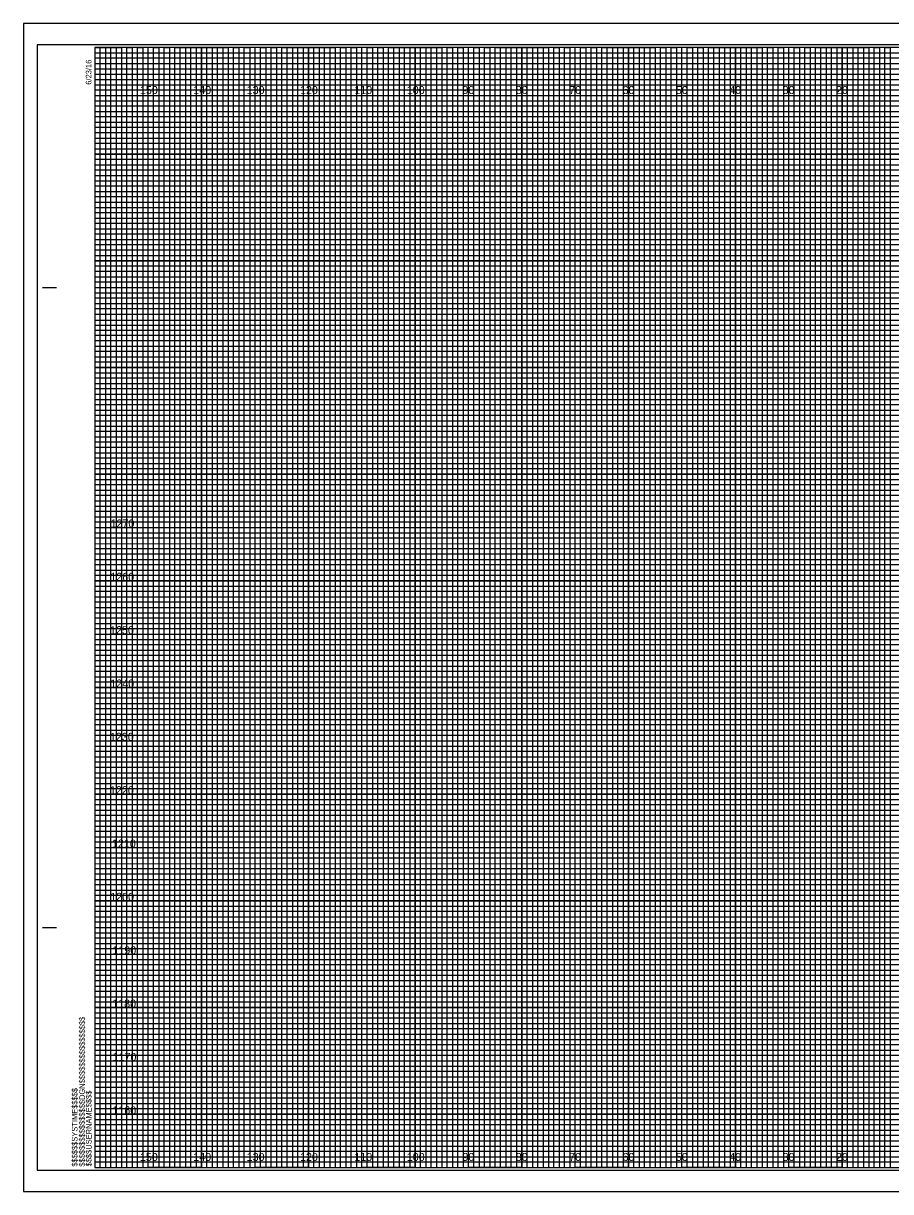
# Model space of a CAD drawing. Extents: x -13 to 323, y 215 to 434.
# Drawn here: x -13.4 to 149.1, y 215.5 to 434.5 of the extents above; entities that cross this region are included whole.
import ezdxf

# ---------------------------------------------------------------- set-up
doc = ezdxf.new("R2010")
doc.units = 0
for name, color, linetype in [('Exist Cross Section Cell', 7, 'Continuous'), ('Exist XS Center Line Elevation Label', 7, 'Continuous'), ('Exist XS Ground Line', 7, 'Continuous'), ('Prop XS Finish Grade', 7, 'Continuous'), ('Prop XS Finish Grade Earthwork', 7, 'Continuous'), ('Prop XS Finish Grade Pavement', 7, 'Continuous'), ('Prop XS Side Slope Text', 7, 'Continuous'), ('Prop XS Subgrade Earthwork', 7, 'Continuous'), ('Prop XSC Text', 7, 'Continuous'), ('Scratch_Level_5', 7, 'Continuous'), ('Typical Curb CELL', 7, 'Continuous')]:
    doc.layers.add(name, color=color, linetype=linetype)

msp = doc.modelspace()

# ---------------------------------------------------------------- linework, layer by layer
at = {"layer": 'Exist Cross Section Cell'}
for points in [[(0, 430), (5, 430), (5, 220), (15, 220), (15, 430), (25, 430), (25, 220), (35, 220), (35, 430), (45, 430), (45, 220), (55, 220), (55, 430), (65, 430), (65, 220), (75, 220), (75, 430), (85, 430), (85, 220), (95, 220), (95, 430), (105, 430), (105, 220), (115, 220), (115, 430), (125, 430), (125, 220), (135, 220), (135, 430), (145, 430), (145, 220), (155, 220)], [(0, 425), (275, 425)], [(0, 405), (320, 405), (320, 415), (0, 415)], [(0, 385), (320, 385), (320, 395), (0, 395)], [(0, 365), (320, 365), (320, 375), (0, 375)], [(0, 345), (320, 345), (320, 355), (0, 355)], [(0, 325), (320, 325), (320, 335), (0, 335)], [(0, 305), (320, 305), (320, 315), (0, 315)], [(0, 285), (320, 285), (320, 295), (0, 295)], [(0, 265), (320, 265), (320, 275), (0, 275)], [(0, 245), (320, 245), (320, 255), (0, 255)], [(0, 225), (320, 225), (320, 235), (0, 235)]]:
    msp.add_lwpolyline(points, dxfattribs=at)
at = {"layer": 'Exist XS Center Line Elevation Label'}
for p, q in [((10, 430), (0, 430)), ((10, 220), (10, 430)), ((30, 430), (20, 430)), ((20, 430), (20, 220)), ((30, 220), (30, 430)), ((50, 430), (40, 430)), ((40, 430), (40, 220)), ((50, 220), (50, 430)), ((70, 430), (60, 430)), ((60, 430), (60, 220)), ((70, 220), (70, 430)), ((90, 430), (80, 430)), ((80, 430), (80, 220)), ((90, 220), (90, 430)), ((110, 430), (100, 430)), ((100, 430), (100, 220)), ((110, 220), (110, 430)), ((130, 430), (120, 430)), ((120, 430), (120, 220)), ((130, 220), (130, 430)), ((150, 430), (140, 430)), ((140, 430), (140, 220)), ((20, 220), (10, 220)), ((40, 220), (30, 220)), ((60, 220), (50, 220)), ((80, 220), (70, 220)), ((100, 220), (90, 220)), ((120, 220), (110, 220)), ((140, 220), (130, 220))]:
    msp.add_line(p, q, dxfattribs=at)
for points in [[(0, 420), (320, 420), (320, 410), (0, 410)], [(0, 400), (320, 400), (320, 390), (0, 390)], [(0, 380), (320, 380), (320, 370), (0, 370)], [(0, 360), (320, 360), (320, 350), (0, 350)], [(0, 340), (320, 340), (320, 330), (0, 330)], [(0, 320), (320, 320), (320, 310), (0, 310)], [(0, 300), (320, 300), (320, 290), (0, 290)], [(0, 280), (320, 280), (320, 270), (0, 270)], [(0, 260), (320, 260), (320, 250), (0, 250)], [(0, 240), (320, 240), (320, 230), (0, 230)]]:
    msp.add_lwpolyline(points, dxfattribs=at)
at = {"layer": 'Prop XS Finish Grade'}
msp.add_lwpolyline([(-10.8, 219.5), (322.4, 219.5), (322.4, 430.5), (-10.8, 430.5)], close=True, dxfattribs=at)
at = {"layer": 'Prop XS Finish Grade Earthwork'}
for p, q in [((10, 220), (10, 430)), ((20, 220), (20, 430)), ((30, 220), (30, 430)), ((40, 220), (40, 430)), ((50, 220), (50, 430)), ((60, 220), (60, 430)), ((70, 220), (70, 430)), ((80, 220), (80, 430)), ((90, 220), (90, 430)), ((100, 220), (100, 430)), ((110, 220), (110, 430)), ((120, 220), (120, 430)), ((130, 220), (130, 430)), ((140, 220), (140, 430)), ((0, 420), (320, 420)), ((0, 410), (320, 410)), ((0, 400), (320, 400)), ((0, 390), (320, 390)), ((0, 380), (320, 380)), ((0, 370), (320, 370)), ((0, 360), (320, 360)), ((0, 350), (320, 350)), ((0, 340), (320, 340)), ((0, 330), (320, 330)), ((0, 320), (320, 320)), ((0, 310), (320, 310)), ((0, 300), (320, 300)), ((0, 290), (320, 290)), ((0, 280), (320, 280)), ((0, 270), (320, 270)), ((0, 260), (320, 260)), ((0, 250), (320, 250)), ((0, 240), (320, 240)), ((0, 230), (320, 230))]:
    msp.add_line(p, q, dxfattribs=at)
at = {"layer": 'Prop XS Finish Grade Pavement'}
for p, q in [((-9.8, 385), (-7.3, 385)), ((-9.7, 385), (-7.2, 385)), ((-9.8, 265), (-7.3, 265)), ((-9.7, 265), (-7.2, 265)), ((0, 220), (0, 220)), ((0, 220), (0, 220)), ((0, 220), (0, 220)), ((0, 220), (0, 220)), ((0, 220), (0, 220)), ((0, 220), (0, 220)), ((0, 220), (0, 220))]:
    msp.add_line(p, q, dxfattribs=at)
msp.add_lwpolyline([(320, 430), (0, 430), (0, 220), (320, 220)], close=True, dxfattribs=at)
at = {"layer": 'Prop XS Subgrade Earthwork'}
msp.add_lwpolyline([(-13.4, 215.5), (323.3, 215.5), (323.3, 434.5), (-13.4, 434.5)], close=True, dxfattribs=at)
at = {"layer": 'Prop XSC Text'}
for p, q in [((323.3, 434.5), (-13.4, 434.5)), ((-13.4, 434.5), (-13.4, 215.5)), ((-13.4, 215.5), (323.3, 215.5))]:
    msp.add_line(p, q, dxfattribs=at)
at = {"layer": 'Scratch_Level_5'}
for p, q in [((0, 429), (260, 429)), ((260, 427.98), (0, 427.98)), ((0, 427.98), (0, 427)), ((0, 427), (260, 427)), ((260, 425.89), (0, 425.89)), ((0, 425.89), (0, 424)), ((0, 424), (320, 424))]:
    msp.add_line(p, q, dxfattribs=at)
for points in [[(0, 423), (270, 423), (320, 423), (320, 422), (0, 422)], [(0, 421), (320, 421), (320, 419), (0, 419)], [(0, 418), (320, 418), (320, 417), (0, 416.98)], [(0, 416), (320, 416), (320, 414), (0, 414)], [(0, 413), (320, 413), (320, 412), (0, 412)], [(0, 411), (320, 411), (320, 409), (0, 409)], [(0, 408), (320, 408), (320, 407), (0, 407)], [(0, 406), (320, 406), (320, 404), (0, 404)], [(0, 403), (320, 403), (320, 402), (0, 402)], [(0, 401), (320, 401), (320, 399), (0, 399)], [(0, 398), (320, 398), (320, 397), (0, 397)], [(0, 396), (320, 396), (320, 393.95), (320, 393), (320, 392), (0, 392)], [(0, 394), (320, 394), (320, 393), (0, 393)], [(0, 391), (320, 391), (320, 389), (0, 389.03)], [(0, 389.03), (320, 389), (320, 388), (0, 388)], [(0, 387), (320, 387), (320, 386), (0, 386)], [(0, 384), (320, 384), (320, 383), (0, 383)], [(0, 382), (320, 382), (320, 381), (0, 381)], [(-0.07, 378.89), (320, 378.89), (320, 377.88), (-0.07, 377.88)], [(0, 377), (320, 377), (320, 376), (0, 376)], [(0, 374), (320, 374), (320, 373), (0, 373)], [(0, 372), (320, 372), (320, 371), (0, 371)], [(0, 369), (320, 369), (320, 368), (0, 368)], [(0, 367), (320, 367), (320, 366), (0, 366)], [(0, 364), (320, 364), (320, 363), (0, 363)], [(0, 362), (320, 362), (320, 361), (0, 361)], [(0, 359), (320, 359), (319.99, 357.98), (0, 358)], [(0, 357), (320, 357), (320, 356), (0, 356)], [(0, 354), (320, 354), (320, 353), (0, 353)], [(0, 352), (320, 352), (320, 351), (0, 351)], [(0, 349), (320, 349), (320, 348), (0, 348)], [(0, 347), (320, 347), (320, 346), (0, 346)], [(0, 344), (320, 344), (320, 343), (0, 343)], [(0, 342), (320, 342), (320, 341), (0, 341)], [(0, 339), (320, 339), (320, 338), (0, 338)], [(0, 336.99), (320.07, 336.91), (320, 336), (0, 336)], [(0, 334), (320, 334), (320, 333), (0, 333)], [(0, 332), (320, 332), (320, 331), (0, 331)], [(0, 329), (320, 329), (320, 328), (0, 328)], [(0, 327), (320, 327), (320, 326), (0, 326)], [(0, 324), (320, 324), (320, 323), (0, 323)], [(0, 322), (320, 322), (320, 321), (0, 321)], [(0, 319), (320, 319), (320, 318), (0, 318)], [(0, 317), (320, 317), (320, 316), (0, 316)], [(0, 314), (320, 314), (320, 313), (0, 313)], [(0, 312), (320, 312), (320, 311), (0, 311)], [(0, 309), (320, 309), (320, 308), (0, 308)], [(0, 307), (320, 307), (320, 306), (0, 306)], [(0, 304), (320, 304), (320, 303), (0, 303)], [(0, 302), (320, 302), (320, 301), (0, 301)], [(0, 299), (320, 299), (319.99, 297.98), (0, 298)], [(0, 297), (320, 297), (320, 296), (0, 296)], [(0, 294), (320, 294), (320, 293), (0, 293)], [(0, 292), (320, 292), (320, 291), (0, 291)], [(0, 289), (320, 289), (320, 288), (0, 288)], [(0, 287), (320, 287), (320, 286), (0, 286)], [(0, 284), (320, 284), (320, 283), (0, 283)], [(0, 282), (320, 282), (320, 281), (0, 281)], [(0, 279), (320, 279), (320, 278), (0, 278)], [(0, 276.99), (320.07, 276.91), (320, 276), (0, 276)], [(0, 274), (320, 274), (320, 273), (0, 273)], [(0, 272), (320, 272), (320, 271), (0, 271)], [(0, 269), (320, 269), (320, 268), (0, 268)], [(0, 267), (320, 267), (320, 266), (0, 266)], [(0, 264), (320, 264), (320, 263), (0, 263)], [(0, 262), (320, 262), (320, 261), (0, 261)], [(0, 259), (320, 259), (320, 258), (0, 258)], [(0, 257), (320, 257), (320, 256), (0, 256)], [(0, 254), (320, 254), (320, 253), (0, 253)], [(0, 252), (320, 252), (320, 251), (0, 251)], [(0, 249), (320, 249), (320, 248), (0, 248)], [(0, 247), (320, 247), (320, 246), (0, 246)], [(0, 244), (320, 244), (320, 243), (0, 243)], [(0, 242), (320, 242), (320, 241), (0, 241)], [(0, 239), (320, 239), (320, 238), (0, 238)], [(0, 237), (320, 237), (320, 236), (0, 236)], [(0, 234), (320, 234), (320, 233), (0, 233)], [(0, 232), (320, 232), (320, 231), (0, 231)], [(0, 229), (320, 229), (320, 228), (0, 228)], [(0, 227), (320, 227), (320, 226), (0, 226)], [(0, 224), (320, 224), (320, 223), (0, 223)], [(0, 222), (320, 222), (320, 221), (0, 221)]]:
    msp.add_lwpolyline(points, dxfattribs=at)
at = {"layer": 'Typical Curb CELL'}
for points in [[(0, 220), (1, 220), (1, 430), (2, 430), (2, 220)], [(2, 220), (3, 220), (3, 430), (4, 430), (4, 220)], [(5, 220), (6, 220), (6, 430), (7, 430), (7, 220)], [(7, 220), (8, 220), (8, 430), (9, 430), (9, 220)], [(10, 220), (11, 220), (11, 430), (12, 430), (12, 220)], [(12, 220), (13, 220), (13, 430), (14, 430), (14, 220)], [(15, 220), (16, 220), (16, 430), (17, 430), (17, 220)], [(17, 220), (18, 220), (18, 430), (19, 430), (19, 220)], [(20, 220), (21, 220), (21, 430), (22, 430), (22, 220)], [(22, 220), (23, 220), (23, 430), (24, 430), (24, 220)], [(25, 220), (26, 220), (26, 430), (27, 430), (27, 220)], [(27, 220), (28, 220), (28, 430), (29, 430), (29, 220)], [(30, 220), (31, 220), (31, 430), (32, 430), (32, 220)], [(32, 220), (33, 220), (33, 430), (34, 430), (34, 220)], [(35, 220), (36, 220), (36, 430), (37, 430), (37, 220)], [(37, 220), (38, 220), (38, 430), (39, 430), (39, 220)], [(40, 220), (41, 220), (41, 430), (42, 430), (42, 220)], [(42, 220), (43, 220), (43, 430), (44, 430), (44, 220)], [(45, 220), (46, 220), (46, 430), (47, 430), (47, 220)], [(47, 220), (48, 220), (48, 430), (49, 430), (49, 220)], [(50, 220), (51, 220), (51, 430), (52, 430), (52, 220)], [(52, 220), (53, 220), (53, 430), (54, 430), (54, 220)], [(55, 220), (56, 220), (56, 430), (57, 430), (57, 220)], [(57, 220), (58, 220), (58, 430), (59, 430), (59, 220)], [(60, 220), (61, 220), (61, 430), (62, 430), (62, 220)], [(62, 220), (63, 220), (63, 430), (64, 430), (64, 220)], [(65, 220), (66, 220), (66, 430), (67, 430), (67, 220)], [(67, 220), (68, 220), (68, 430), (69, 430), (69, 220)], [(70, 220), (71, 220), (71, 430), (72, 430), (72, 220)], [(72, 220), (73, 220), (73, 430), (74, 430), (74, 220)], [(75, 220), (76, 220), (76, 430), (77, 430), (77, 220)], [(77, 220), (78, 220), (78, 430), (79, 430), (79, 220)], [(80, 220), (81, 220), (81, 430), (82, 430), (82, 220)], [(82, 220), (83, 220), (83, 430), (84, 430), (84, 220)], [(85, 220), (86, 220), (86, 430), (87, 430), (87, 220)], [(87, 220), (88, 220), (88, 430), (89, 430), (89, 220)], [(90, 220), (91, 220), (91, 430), (92, 430), (92, 220)], [(92, 220), (93, 220), (93, 430), (94, 430), (94, 220)], [(95, 220), (96, 220), (96, 430), (97, 430), (97, 220)], [(97, 220), (98, 220), (98, 430), (99, 430), (99, 220)], [(100, 220), (101, 220), (101, 430), (102, 430), (102, 220)], [(102, 220), (103, 220), (103, 430), (104, 430), (104, 220)], [(105, 220), (106, 220), (106, 430), (107, 430), (107, 220)], [(107, 220), (108, 220), (108, 430), (109, 430), (109, 220)], [(110, 220), (111, 220), (111, 430), (112, 430), (112, 220)], [(112, 220), (113, 220), (113, 430), (114, 430), (114, 220)], [(115, 220), (116, 220), (116, 430), (117, 430), (117, 220)], [(117, 220), (118, 220), (118, 430), (119, 430), (119, 220)], [(120, 220), (121, 220), (121, 430), (122, 430), (122, 220)], [(122, 220), (123, 220), (123, 430), (124, 430), (124, 220)], [(125, 220), (126, 220), (126, 430), (127, 430), (127, 220)], [(127, 220), (128, 220), (128, 430), (129, 430), (129, 220)], [(130, 220), (131, 220), (131, 430), (132, 430), (132, 220)], [(132, 220), (133, 220), (133, 430), (134, 430), (134, 220)], [(135, 220), (136, 220), (136, 430), (137, 430), (137, 220)], [(137, 220), (138, 220), (138, 430), (139, 430), (139, 220)], [(140, 220), (141, 220), (141, 430), (142, 430), (142, 220)], [(142, 220), (143, 220), (143, 430), (144, 430), (144, 220)], [(145, 220), (146, 220), (146, 430), (147, 430), (147, 220)], [(147, 220), (148, 220), (148, 430), (149, 430), (149, 220)]]:
    msp.add_lwpolyline(points, dxfattribs=at)

# ---------------------------------------------------------------- texts
at = {"layer": 'Exist XS Ground Line'}
for s, p in [('150', (8.44, 421.25)), ('140', (18.44, 421.25)), ('130', (28.44, 421.25)), ('120', (38.44, 421.25)), ('110', (48.62, 421.25)), ('100', (58.44, 421.25)), ('90', (68.86, 421.25)), ('80', (78.86, 421.25)), ('70', (88.86, 421.25)), ('60', (98.86, 421.25)), ('50', (108.86, 421.25)), ('40', (118.86, 421.25)), ('30', (128.86, 421.25)), ('20', (138.86, 421.25)), ('150', (8.44, 221.25)), ('140', (18.44, 221.25)), ('130', (28.44, 221.25)), ('120', (38.44, 221.25)), ('110', (48.62, 221.25)), ('100', (58.44, 221.25)), ('90', (68.86, 221.25)), ('80', (78.86, 221.25)), ('70', (88.86, 221.25)), ('60', (98.86, 221.25)), ('50', (108.86, 221.25)), ('40', (118.86, 221.25)), ('30', (128.86, 221.25)), ('20', (138.86, 221.25))]:
    msp.add_text(s, height=1.5, dxfattribs=at).set_placement(p)
at = {"layer": 'Prop XS Finish Grade Pavement'}
for s, p in [('6/23/16', (-0.65, 423)), ('$$$$$$$$$$$$$$$$DGN$$$$$$$$$$$$$$$$', (-1.88, 220.18)), ('$$$$$$SYSTIME$$$$$', (-3.26, 220.18)), ('$$$$USERNAME$$$$', (-0.62, 220.23))]:
    msp.add_text(s, height=1.05, rotation=90, dxfattribs=at).set_placement(p)
at = {"layer": 'Prop XS Side Slope Text'}
for s, p in [('1270', (2.93, 340)), ('1260', (2.9, 330)), ('1250', (2.85, 320)), ('1240', (2.9, 310)), ('1230', (2.82, 300)), ('1220', (2.83, 290)), ('1210', (3.2, 280)), ('1200', (2.87, 270)), ('1190', (3.28, 260)), ('1180', (3.25, 250)), ('1170', (3.31, 240)), ('1160', (3.28, 230))]:
    msp.add_text(s, height=1.5, dxfattribs=at).set_placement(p)

doc.saveas('drawing.dxf')
